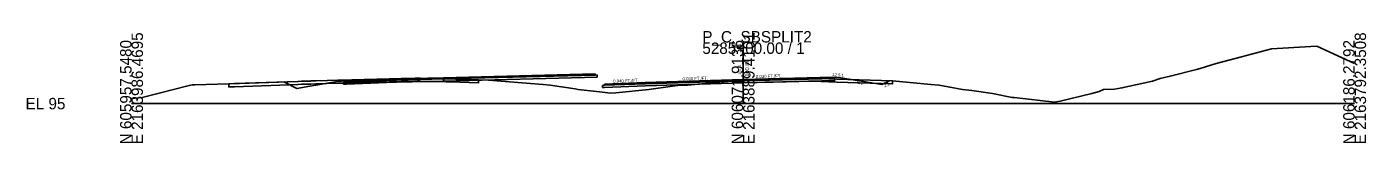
# Model space of a CAD drawing. Extents: x -26 to 1303, y -10 to 12033.
# Drawn here: x -25.7 to 302.8, y 2990.3 to 3017.8 of the extents above; entities that cross this region are included whole.
import ezdxf

# ---------------------------------------------------------------- set-up
doc = ezdxf.new("R2010")
doc.units = 0
for name, color, linetype in [('RD_GPK_XS_Cell', 7, 'Continuous'), ('RD_XS_Base', 7, 'Continuous'), ('RD_XS_ExGround', 7, 'Continuous'), ('RD_XS_ExPaveRet', 7, 'Continuous'), ('RD_XS_Greenside', 7, 'Continuous'), ('RD_XS_Pave', 7, 'Continuous'), ('RD_XS_PaveOvlay_CP', 7, 'Continuous'), ('RD_XS_TieSlope', 7, 'Continuous'), ('RD_XS_TX_Elev_EX', 7, 'Continuous'), ('RD_XS_TX_Elev_PR', 7, 'Continuous'), ('RD_XS_TX_ShdSlope', 7, 'Continuous'), ('RD_XS_TX_Slope', 7, 'Continuous')]:
    doc.layers.add(name, color=color, linetype=linetype)

msp = doc.modelspace()

# ---------------------------------------------------------------- linework, layer by layer
at = {"layer": 'RD_GPK_XS_Cell'}
for p, q in [((150, 3000), (150, 3015)), ((0, 3000), (150, 3000)), ((150, 3000), (300, 3000))]:
    msp.add_line(p, q, dxfattribs=at)
at = {"layer": 'RD_XS_Base'}
for p, q in [((76.53, 3006.04), (114.19, 3007.02)), ((114.19, 3006.52), (76.53, 3005.54)), ((76.53, 3005.54), (76.53, 3006.2)), ((76.53, 3006.2), (76.53, 3006.2)), ((76.53, 3006.2), (76.53, 3006.2)), ((76.53, 3006.2), (76.53, 3006.04)), ((100.53, 3006.66), (100.53, 3006.66)), ((100.53, 3006.66), (100.53, 3006.66)), ((100.53, 3006.16), (100.53, 3006.16)), ((100.53, 3006.16), (100.53, 3006.16)), ((113.69, 3007), (113.69, 3007)), ((114.19, 3007.02), (114.19, 3006.52)), ((114.19, 3006.98), (114.19, 3006.98)), ((172.5, 3006.19), (172.5, 3005.69)), ((52.03, 3005.23), (52.02, 3005.23)), ((52.02, 3005.23), (52.02, 3004.73)), ((52.02, 3004.73), (52.02, 3004.73)), ((52.02, 3004.73), (52.03, 3004.73)), ((52.52, 3005.25), (52.03, 3005.23)), ((52.03, 3004.73), (52.52, 3004.75)), ((52.73, 3005.25), (52.52, 3005.25)), ((52.52, 3004.75), (52.73, 3004.75)), ((64.52, 3005.73), (52.73, 3005.25)), ((52.73, 3004.75), (64.52, 3005.23)), ((65.01, 3005.74), (64.52, 3005.73)), ((64.52, 3005.23), (65.01, 3005.24)), ((76.53, 3006.04), (65.01, 3005.74)), ((65.01, 3005.24), (76.53, 3005.54)), ((76.53, 3006.04), (76.53, 3006.04)), ((76.53, 3005.54), (76.53, 3006.04)), ((76.53, 3006.04), (76.53, 3006.04)), ((76.53, 3006.04), (76.53, 3006.04)), ((76.53, 3005.54), (76.53, 3005.54)), ((116, 3004.49), (115.5, 3004.47)), ((115.5, 3004.47), (115.5, 3004.47)), ((115.5, 3004.47), (115.5, 3003.97)), ((115.5, 3003.97), (116, 3003.99)), ((126, 3004.89), (116, 3004.49)), ((116, 3004.49), (116, 3004.49)), ((116, 3003.99), (126, 3004.39)), ((116, 3003.99), (116, 3003.99)), ((150, 3005.56), (126, 3004.89)), ((126, 3004.39), (150, 3005.06)), ((126, 3004.89), (126, 3004.89)), ((126, 3004.39), (126, 3004.39)), ((150, 3005.56), (162, 3005.9)), ((150, 3005.06), (150, 3005.72)), ((150, 3005.72), (150, 3005.72)), ((150, 3005.72), (150, 3005.72)), ((150, 3005.72), (150, 3005.56)), ((172.5, 3005.69), (150, 3005.06)), ((150, 3005.56), (150, 3005.56)), ((150, 3005.06), (150, 3005.56)), ((150, 3005.56), (150, 3005.56)), ((150, 3005.56), (150, 3005.56)), ((150, 3005.06), (150, 3005.06)), ((162, 3005.9), (162, 3005.9)), ((162, 3005.9), (162, 3005.9)), ((162, 3005.4), (162, 3005.4)), ((162, 3005.4), (162, 3005.4))]:
    msp.add_line(p, q, dxfattribs=at)
at = {"layer": 'RD_XS_ExGround'}
msp.add_lwpolyline([(0, 3001.25), (2.63, 3001.53), (14.14, 3004.41), (14.93, 3004.62), (15.49, 3004.63), (23.86, 3004.85), (24.14, 3004.86), (40.78, 3005.46), (41.73, 3005.48), (42.67, 3005.5), (45.27, 3005.59), (50.91, 3005.75), (63.21, 3006.08), (69.57, 3006.24), (69.58, 3006.22), (69.58, 3006.2), (69.7, 3006.21), (70.86, 3006.22), (73.78, 3006.15), (85.14, 3005.86), (87.58, 3005.73), (100.93, 3004.68), (102.65, 3004.51), (108.78, 3003.62), (109.53, 3003.5), (114.06, 3002.96), (117.58, 3002.52), (118.81, 3002.66), (126.88, 3003.5), (132.69, 3004.31), (133.96, 3004.47), (136.34, 3004.56), (144.29, 3005.29), (147.3, 3005.5), (151.24, 3005.85), (153.43, 3005.92), (155.36, 3005.97), (157.38, 3006), (166.84, 3006.22), (167.23, 3006.22), (172.97, 3006.02), (186.64, 3005.58), (196.05, 3004.7), (198.13, 3004.5), (200.28, 3004.14), (203.81, 3003.5), (206.12, 3003.19), (211.15, 3002.48), (216.01, 3001.53), (216.15, 3001.5), (216.47, 3001.47), (226.37, 3000.32), (227.79, 3000.62), (235.58, 3002.5), (237.36, 3002.99), (238.38, 3003.49), (241.09, 3003.56), (242.92, 3003.85), (250.4, 3005.48), (252.29, 3006.15), (254.73, 3006.77), (261.25, 3008.36), (262.08, 3008.59), (266.01, 3009.84), (272.25, 3011.45), (279.58, 3013.48), (289.23, 3014), (290.71, 3014.12), (293.92, 3012.65), (300, 3009.83)], dxfattribs=at)
at = {"layer": 'RD_XS_ExPaveRet'}
for points in [[(85.14, 3005.86), (80.54, 3005.98), (73.78, 3006.15), (71.66, 3006.2), (70.86, 3006.22), (70.03, 3006.22), (69.7, 3006.21), (69.67, 3006.21), (69.58, 3006.2), (69.58, 3006.21), (69.58, 3006.22), (69.57, 3006.23), (69.57, 3006.24), (66.13, 3006.15), (63.21, 3006.08), (51.78, 3005.77), (50.91, 3005.75), (50.6, 3005.74), (45.27, 3005.59), (45.22, 3005.59), (44.01, 3005.55), (43.88, 3005.54), (43.73, 3005.54), (42.67, 3005.5), (41.72, 3005.48), (40.85, 3005.46), (40.82, 3005.46), (40.78, 3005.46), (25.26, 3004.9), (24.14, 3004.86), (23.86, 3004.85), (23.86, 3004.85), (23.86, 3004.85), (23.86, 3004.85), (23.86, 3004.77), (23.86, 3004.1), (23.86, 3004.1), (23.86, 3004.1), (23.86, 3004.1), (24.14, 3004.11), (25.26, 3004.15), (40.78, 3004.71), (40.82, 3004.71), (40.85, 3004.71), (41.72, 3004.73), (42.67, 3004.75), (43.73, 3004.79), (43.88, 3004.79), (44.01, 3004.8), (45.22, 3004.84), (45.27, 3004.84), (50.6, 3004.99), (50.91, 3005), (51.78, 3005.02), (63.21, 3005.33), (66.13, 3005.4), (69.57, 3005.49), (69.57, 3005.48), (69.58, 3005.47), (69.58, 3005.46), (69.58, 3005.45), (69.67, 3005.46), (69.7, 3005.46), (70.03, 3005.47), (70.86, 3005.47), (71.66, 3005.45), (73.78, 3005.4), (80.54, 3005.23), (85.14, 3005.11), (85.14, 3005.11), (85.14, 3005.11), (85.14, 3005.53), (85.14, 3005.86), (85.14, 3005.86), (85.14, 3005.86)], [(85.14, 3005.86), (80.54, 3005.98), (73.78, 3006.15), (71.66, 3006.2), (70.86, 3006.22), (70.03, 3006.22), (69.7, 3006.21), (69.67, 3006.21), (69.58, 3006.2), (69.58, 3006.21), (69.58, 3006.22), (69.57, 3006.23), (69.57, 3006.24), (66.13, 3006.15), (63.21, 3006.08), (51.78, 3005.77), (50.91, 3005.75), (50.6, 3005.74), (45.27, 3005.59), (45.22, 3005.59), (44.01, 3005.55), (43.88, 3005.54), (43.73, 3005.54), (42.67, 3005.5), (41.72, 3005.48), (40.85, 3005.46), (40.82, 3005.46), (40.78, 3005.46), (25.26, 3004.9), (24.14, 3004.86), (23.86, 3004.85), (23.86, 3004.85), (23.86, 3004.85), (23.86, 3004.77), (23.86, 3004.1), (23.86, 3004.1), (23.86, 3004.1), (24.14, 3004.11), (25.26, 3004.15), (40.78, 3004.71), (40.82, 3004.71), (40.85, 3004.71), (41.72, 3004.73), (42.67, 3004.75), (43.73, 3004.79), (43.88, 3004.79), (44.01, 3004.8), (45.22, 3004.84), (45.27, 3004.84), (50.6, 3004.99), (50.91, 3005), (51.78, 3005.02), (63.21, 3005.33), (66.13, 3005.4), (69.57, 3005.49), (69.57, 3005.48), (69.58, 3005.47), (69.58, 3005.46), (69.58, 3005.45), (69.67, 3005.46), (69.7, 3005.46), (70.03, 3005.47), (70.86, 3005.47), (71.66, 3005.45), (73.78, 3005.4), (80.54, 3005.23), (85.14, 3005.11), (85.14, 3005.11), (85.14, 3005.53), (85.14, 3005.86), (85.14, 3005.86)], [(186.64, 3005.58), (186.64, 3005.58), (186.64, 3005.58), (186.64, 3004.83), (186.64, 3004.83), (172.97, 3005.27), (172.97, 3005.27), (167.23, 3005.47), (167.23, 3005.47), (166.84, 3005.47), (166.84, 3005.47), (157.38, 3005.25), (157.38, 3005.25), (157.38, 3005.25), (155.36, 3005.22), (153.43, 3005.17), (153.43, 3005.17), (151.24, 3005.1), (151.24, 3005.1), (151.24, 3005.85), (151.24, 3005.85), (151.24, 3005.85), (153.43, 3005.92), (153.43, 3005.92), (155.36, 3005.97), (157.38, 3006), (157.38, 3006), (157.38, 3006), (166.84, 3006.22), (166.84, 3006.22), (167.23, 3006.22), (167.23, 3006.22), (172.97, 3006.02), (172.97, 3006.02), (186.64, 3005.58)], [(172.97, 3006.02), (167.23, 3006.22), (166.84, 3006.22), (157.38, 3006), (155.36, 3005.97), (153.43, 3005.92), (151.24, 3005.85), (151.24, 3005.85), (151.24, 3005.1), (151.24, 3005.1), (153.43, 3005.17), (155.36, 3005.22), (157.38, 3005.25), (166.84, 3005.47), (167.23, 3005.47), (172.97, 3005.27), (186.64, 3004.83), (186.64, 3005.58), (172.97, 3006.02)]]:
    msp.add_lwpolyline(points, dxfattribs=at)
at = {"layer": 'RD_XS_Greenside'}
for p, q in [((174, 3006.33), (184, 3004.67)), ((40.52, 3003.74), (37.32, 3005.34)), ((43.73, 3004.27), (40.52, 3003.74)), ((50.52, 3005.4), (43.73, 3004.27)), ((184, 3004.67), (185.88, 3005.61))]:
    msp.add_line(p, q, dxfattribs=at)
at = {"layer": 'RD_XS_Pave'}
for p, q in [((76.53, 3006.35), (65.01, 3006.06)), ((65.01, 3005.9), (76.53, 3006.2)), ((76.53, 3006.2), (65.01, 3005.9)), ((113.69, 3007.32), (76.53, 3006.35)), ((113.69, 3007.16), (76.53, 3006.2)), ((76.53, 3006.2), (113.69, 3007.16)), ((76.53, 3006.04), (113.69, 3007)), ((76.53, 3006.35), (76.53, 3006.35)), ((76.53, 3006.2), (76.53, 3006.2)), ((76.53, 3006.2), (76.53, 3006.2)), ((76.53, 3006.2), (76.53, 3006.04)), ((76.53, 3006.2), (76.53, 3006.2)), ((76.53, 3006.04), (76.53, 3006.2)), ((76.53, 3006.2), (76.53, 3006.2)), ((76.53, 3006.2), (76.53, 3006.2)), ((100.53, 3006.98), (100.53, 3006.98)), ((100.53, 3006.98), (100.53, 3006.98)), ((100.53, 3006.82), (100.53, 3006.82)), ((100.53, 3006.82), (100.53, 3006.82)), ((100.53, 3006.82), (100.53, 3006.82)), ((100.53, 3006.82), (100.53, 3006.82)), ((100.53, 3006.66), (100.53, 3006.66)), ((100.53, 3006.66), (100.53, 3006.66)), ((113.69, 3007.16), (113.69, 3007.32)), ((113.69, 3007.32), (113.69, 3007.32)), ((113.69, 3007), (113.69, 3007.16)), ((113.69, 3007.16), (113.69, 3007.16)), ((172, 3006.49), (150, 3005.88)), ((150, 3005.72), (172, 3006.33)), ((150, 3005.56), (172.5, 3006.19)), ((162, 3006.21), (162, 3006.21)), ((162, 3006.21), (162, 3006.21)), ((172, 3006.33), (172, 3006.49)), ((172, 3006.18), (172, 3006.33)), ((172, 3006.33), (172, 3006.33)), ((52.73, 3005.57), (52.52, 3005.56)), ((52.52, 3005.56), (52.52, 3005.41)), ((52.52, 3005.41), (52.52, 3005.41)), ((52.52, 3005.41), (52.73, 3005.41)), ((52.73, 3005.41), (52.52, 3005.41)), ((52.52, 3005.41), (52.52, 3005.25)), ((52.52, 3005.25), (52.52, 3005.25)), ((52.52, 3005.25), (52.73, 3005.25)), ((64.52, 3006.04), (52.73, 3005.57)), ((52.73, 3005.41), (64.52, 3005.88)), ((64.52, 3005.88), (52.73, 3005.41)), ((52.73, 3005.25), (64.52, 3005.73)), ((65.01, 3006.06), (64.52, 3006.04)), ((64.52, 3005.88), (65.01, 3005.9)), ((65.01, 3005.9), (64.52, 3005.88)), ((64.52, 3005.73), (65.01, 3005.74)), ((65.01, 3005.74), (76.53, 3006.04)), ((76.53, 3006.04), (76.53, 3006.04)), ((76.53, 3006.04), (76.53, 3006.04)), ((126, 3005.21), (116, 3004.81)), ((116, 3004.65), (126, 3005.05)), ((126, 3005.05), (116, 3004.65)), ((116, 3004.49), (126, 3004.89)), ((116, 3004.81), (116, 3004.81)), ((116, 3004.81), (116, 3004.65)), ((116, 3004.65), (116, 3004.65)), ((116, 3004.65), (116, 3004.49)), ((150, 3005.88), (126, 3005.21)), ((126, 3005.05), (150, 3005.72)), ((150, 3005.72), (126, 3005.05)), ((126, 3004.89), (150, 3005.56)), ((126, 3005.21), (126, 3005.21)), ((126, 3005.05), (126, 3005.05)), ((126, 3005.05), (126, 3005.05)), ((126, 3004.89), (126, 3004.89)), ((162, 3006.05), (150, 3005.72)), ((150, 3005.88), (150, 3005.88)), ((150, 3005.72), (150, 3005.72)), ((150, 3005.72), (150, 3005.72)), ((150, 3005.72), (150, 3005.56)), ((150, 3005.72), (150, 3005.72)), ((150, 3005.56), (150, 3005.72)), ((150, 3005.72), (150, 3005.72)), ((150, 3005.72), (150, 3005.72)), ((150, 3005.56), (150, 3005.56)), ((150, 3005.56), (150, 3005.56)), ((162, 3006.05), (162, 3006.05)), ((162, 3006.05), (162, 3006.05)), ((162, 3006.05), (162, 3006.05)), ((162, 3006.05), (162, 3006.05)), ((162, 3005.9), (162, 3005.9)), ((162, 3005.9), (162, 3005.9))]:
    msp.add_line(p, q, dxfattribs=at)
at = {"layer": 'RD_XS_PaveOvlay_CP'}
for p, q in [((76.53, 3006.35), (65.01, 3006.06)), ((113.69, 3007.32), (76.53, 3006.35)), ((76.53, 3006.35), (76.53, 3006.35)), ((100.53, 3006.98), (100.53, 3006.98)), ((100.53, 3006.98), (100.53, 3006.98)), ((162, 3006.21), (150, 3005.88)), ((162, 3006.21), (162, 3006.21)), ((162, 3006.21), (162, 3006.21)), ((52.73, 3005.57), (52.52, 3005.56)), ((64.52, 3006.04), (52.73, 3005.57)), ((65.01, 3006.06), (64.52, 3006.04)), ((126, 3005.21), (116, 3004.81)), ((150, 3005.88), (126, 3005.21)), ((126, 3005.21), (126, 3005.21)), ((150, 3005.88), (150, 3005.88))]:
    msp.add_line(p, q, dxfattribs=at)
at = {"layer": 'RD_XS_TieSlope'}
for p, q in [((172, 3006.49), (174, 3006.33)), ((52.52, 3005.56), (50.52, 3005.4))]:
    msp.add_line(p, q, dxfattribs=at)

# ---------------------------------------------------------------- texts
at = {"layer": 'RD_GPK_XS_Cell'}
for s, p in [('E 2163986.4695', (2.8, 2990)), ('E 2163889.4101', (152.8, 2990)), ('E 2163792.3508', (302.8, 2990)), ('N 605957.5480', (0, 2990)), ('N 606071.9136', (150, 2990)), ('N 606186.2792', (300, 2990))]:
    msp.add_text(s, height=2.8, rotation=90, dxfattribs=at).set_placement(p)
for s, p in [('P_C_SBSPLIT2', (140, 3015)), ('5285+00.00 / 1', (140, 3012.2)), ('EL 95', (-26, 2998.6))]:
    msp.add_text(s, height=2.8, dxfattribs=at).set_placement(p)
at = {"layer": 'RD_XS_TX_Elev_EX'}
msp.add_text('100.74', height=0.6, rotation=90, dxfattribs=at).set_placement((149.47, 3007.08))
at = {"layer": 'RD_XS_TX_Elev_PR'}
msp.add_text('100.88', height=1, rotation=90, dxfattribs=at).set_placement((151.49, 3006.61))
at = {"layer": 'RD_XS_TX_ShdSlope'}
msp.add_text('12.5:1', height=0.75, rotation=355.4261, dxfattribs=at).set_placement((171.84, 3006.78))
at = {"layer": 'RD_XS_TX_Slope'}
for s, rotation, p in [('0.040 FT./FT.', 2.2906, (118.15, 3005.12)), ('0.030 FT./FT.', 1.7184, (135.16, 3005.71)), ('0.030 FT./FT.', 1.7184, (153.16, 3006.25)), ('6:1', 350.5358, (177.95, 3004.86)), ('2:1', 26.5651, (184.74, 3003.97))]:
    msp.add_text(s, height=0.75, rotation=rotation, dxfattribs=at).set_placement(p)

doc.saveas('drawing.dxf')
